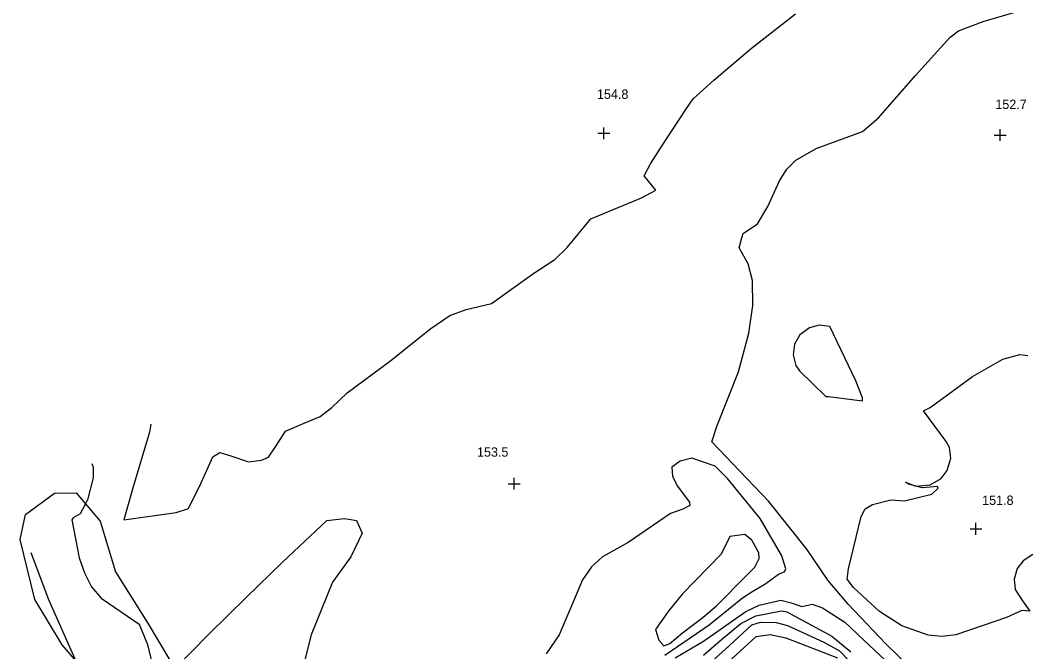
# Model space of a CAD drawing. Extents: x 1467615 to 2003689, y 770235 to 1108726.
# Drawn here: x 2002016.7 to 2002231.5, y 772441.5 to 772576.2 of the extents above; entities that cross this region are included whole.
import ezdxf

# ---------------------------------------------------------------- set-up
doc = ezdxf.new("R2010")
doc.units = 0
for name, color, linetype in [('RD_DTM_Major1', 7, 'Continuous'), ('RD_DTM_Minor1', 7, 'Continuous'), ('RD_DTM_Minor2', 7, 'Continuous'), ('RD_DTM_Obscure', 7, 'Continuous'), ('RD_DTM_Spot_Elev', 7, 'Continuous')]:
    doc.layers.add(name, color=color, linetype=linetype)

msp = doc.modelspace()

# ---------------------------------------------------------------- linework, layer by layer
at = {"layer": 'RD_DTM_Major1'}
for points in [[(2002166.11, 772462.36), (2002157.92, 772453.87), (2002154.87, 772450.14), (2002152.16, 772446.28), (2002152.83, 772444), (2002153.88, 772442.79), (2002155.19, 772443.3), (2002157.86, 772445.53), (2002162.27, 772448.91), (2002165.15, 772451.3), (2002171.7, 772457.89), (2002173.34, 772459.55), (2002174.25, 772461.39), (2002174.15, 772462.61), (2002172.67, 772465.31), (2002171.21, 772466.52), (2002167.98, 772466.13), (2002166.11, 772462.36)], [(2002165.01, 772436.89), (2002173.6, 772444.79), (2002176.56, 772445.18), (2002179.95, 772444.48), (2002190.92, 772440.2)]]:
    msp.add_lwpolyline(points, dxfattribs=at)
at = {"layer": 'RD_DTM_Minor1'}
for points in [[(2002044.54, 772490.04), (2002044.27, 772488.35), (2002040.75, 772476.72), (2002038.81, 772469.64), (2002049.96, 772471.18), (2002052.6, 772472.04), (2002055.31, 772477.54), (2002057.77, 772483.1), (2002059.24, 772483.98), (2002061.57, 772483.33), (2002065.36, 772482.02), (2002068.11, 772482.35), (2002069.61, 772483.02), (2002071.15, 772485.24), (2002073.27, 772488.57), (2002077.24, 772490.27), (2002080.62, 772491.65), (2002083.14, 772493.58), (2002086.43, 772496.71), (2002095.44, 772503.43), (2002104.25, 772510.44), (2002108.26, 772513.21), (2002111.77, 772514.5), (2002117.17, 772515.76), (2002126.21, 772522.26), (2002130.66, 772525.14), (2002133.31, 772527.73), (2002138.36, 772533.86), (2002149.14, 772538.32), (2002152.18, 772539.97), (2002149.75, 772543.03), (2002151.06, 772545.57), (2002153.86, 772549.92), (2002158.75, 772557.37), (2002160.19, 772559.45), (2002164.56, 772563.39), (2002172.59, 772570.25), (2002182.01, 772577.54)], [(2002209.1, 772435.53), (2002201.18, 772443.27), (2002193.23, 772451.64), (2002188.91, 772456.79), (2002184.37, 772463.39), (2002176.33, 772473.59), (2002168.52, 772481.69), (2002164.15, 772486.31), (2002165.27, 772489.78), (2002169.82, 772501.24), (2002172.04, 772509.44), (2002172.9, 772515.36), (2002172.85, 772520.68), (2002171.88, 772524.23), (2002169.99, 772527.67), (2002170.55, 772529.76), (2002170.81, 772530.7), (2002173.87, 772532.76), (2002176.05, 772536.49), (2002178.54, 772541.92), (2002180.14, 772544.41), (2002182.06, 772546.35), (2002186.37, 772548.79), (2002196.27, 772552.42), (2002199.65, 772555.38), (2002207.6, 772564.36), (2002214.96, 772572.57), (2002216.74, 772573.9), (2002221.97, 772575.87), (2002231.41, 772578.68)], [(2002188.46, 772495.97), (2002189.04, 772495.96), (2002196.25, 772495.02), (2002196.28, 772495.65), (2002194.87, 772499.26), (2002189.27, 772510.84), (2002187.06, 772511.13), (2002185, 772510.62), (2002182.92, 772509.09), (2002181.78, 772507.08), (2002181.46, 772504.85), (2002182.07, 772502.54), (2002182.87, 772501.45), (2002188.46, 772495.97)], [(2002232.57, 772462.24), (2002230.53, 772460.9), (2002229.27, 772459.25), (2002228.62, 772457), (2002228.84, 772454.81), (2002230.35, 772452.4), (2002231.93, 772450.17), (2002230.24, 772450.3), (2002226.97, 772448.85), (2002216.17, 772445.11), (2002213.21, 772444.78), (2002210.24, 772445.05), (2002204.62, 772447.03), (2002199.89, 772450.07), (2002194.38, 772455.21), (2002192.98, 772457.01), (2002193.27, 772459.22), (2002195.97, 772470.35), (2002196.82, 772472.02), (2002198.37, 772472.9), (2002202.32, 772473.94), (2002205.2, 772473.71), (2002211.07, 772475.11), (2002212.37, 772476.42), (2002212.23, 772476.79), (2002209.05, 772476.5), (2002206.09, 772477.22), (2002205.43, 772477.67), (2002207.65, 772476.86), (2002210.72, 772477.09), (2002213.01, 772478.47), (2002214.35, 772480.18), (2002215.08, 772482.81), (2002214.79, 772485.08), (2002214.07, 772486.32), (2002209.26, 772492.88), (2002210.66, 772493.63), (2002219.7, 772500.19), (2002226.16, 772503.94), (2002229.8, 772504.91), (2002231.53, 772504.66)], [(2002154.11, 772440.78), (2002163.58, 772447.26), (2002170.7, 772453.04), (2002172.86, 772454.46), (2002175.67, 772456.06), (2002178.36, 772458.07), (2002179.67, 772458.57), (2002179.9, 772459.21), (2002179.05, 772461.99), (2002174.46, 772469.95), (2002167.5, 772478.44), (2002164.84, 772481.11), (2002159.91, 772482.78), (2002157.43, 772482.17), (2002155.63, 772480.87), (2002155.77, 772478.99), (2002156.73, 772476.91), (2002159.39, 772473.39), (2002159.44, 772472.7), (2002157.94, 772471.94), (2002155.31, 772470.97), (2002146.34, 772464.79), (2002140.87, 772461.77), (2002138.47, 772459.62), (2002136.58, 772456.85), (2002133.9, 772450.49), (2002131.59, 772445.11), (2002128.82, 772441.07)], [(2002031.98, 772481.64), (2002032.24, 772480.86), (2002032.25, 772478.64), (2002031.06, 772473.93), (2002030.61, 772473.08)], [(2002049.21, 772437.44), (2002056.93, 772445.27), (2002064.89, 772453.08), (2002072.64, 772460.63), (2002082.1, 772469.53), (2002085.77, 772469.96), (2002086.76, 772469.81), (2002088.37, 772469.54), (2002089.57, 772466.84), (2002087.17, 772461.75), (2002083.28, 772456.35), (2002078.7, 772445.16), (2002077.07, 772438.66)], [(2002156.36, 772440.23), (2002162.35, 772443.76), (2002171.42, 772450.14), (2002174.24, 772451.43), (2002178.89, 772452.53), (2002181.07, 772451.93), (2002183.34, 772451.2), (2002185.55, 772451.66), (2002187.75, 772450.88), (2002192.47, 772447.86), (2002196.46, 772444.04), (2002204.64, 772436.37)], [(2002162.38, 772440.8), (2002166.23, 772444.11), (2002170.32, 772447.56), (2002173.55, 772449.21), (2002178.97, 772450.28), (2002180.16, 772450.03), (2002189.74, 772444.85), (2002193.77, 772441.47)], [(2002161.74, 772437.25), (2002167.9, 772442.84), (2002172.64, 772447.24), (2002174.51, 772447.81), (2002177.86, 772447.73), (2002180.31, 772447.11), (2002187.99, 772443.6), (2002191.35, 772441.74), (2002193.47, 772439.52)]]:
    msp.add_lwpolyline(points, dxfattribs=at)
at = {"layer": 'RD_DTM_Minor2'}
for points in [[(2002030.61, 772473.08), (2002029.48, 772470.91), (2002027.97, 772470.06), (2002027.72, 772469.67), (2002029.3, 772461.58), (2002030.38, 772458.32), (2002031.92, 772455.34), (2002033.96, 772452.98), (2002038.46, 772449.89), (2002042.05, 772447.39), (2002043.84, 772443.04), (2002044.96, 772438.32), (2002046.39, 772437.3), (2002048.93, 772437.16), (2002049.21, 772437.44)], [(2002018.98, 772462.66), (2002022.7, 772452.67), (2002028.31, 772440.02), (2002028.55, 772439.6)]]:
    msp.add_lwpolyline(points, dxfattribs=at)
at = {"layer": 'RD_DTM_Obscure'}
msp.add_lwpolyline([(2002037.57, 772429.15), (2002033.12, 772434.3), (2002025.65, 772442.97), (2002019.8, 772452.67), (2002016.69, 772465.45), (2002017.85, 772470.77), (2002023.98, 772475.34), (2002028.62, 772475.38), (2002033.78, 772469.4), (2002037.03, 772458.54), (2002043.77, 772447.8), (2002048.59, 772439.72), (2002050.26, 772433.61), (2002047.39, 772426.1), (2002037.57, 772429.15)], dxfattribs=at)
at = {"layer": 'RD_DTM_Spot_Elev'}
for p, q in [((2002139.87, 772552.06), (2002142.37, 772552.06)), ((2002141.12, 772550.81), (2002141.12, 772553.31)), ((2002224.36, 772551.69), (2002226.86, 772551.69)), ((2002225.61, 772550.44), (2002225.61, 772552.94)), ((2002122, 772476.11), (2002122, 772478.61)), ((2002120.75, 772477.36), (2002123.25, 772477.36)), ((2002219.2, 772467.73), (2002221.7, 772467.73)), ((2002220.45, 772466.48), (2002220.45, 772468.98))]:
    msp.add_line(p, q, dxfattribs=at)

# ---------------------------------------------------------------- texts
for s, p in [('154.8', (2002139.66, 772559.41)), ('152.7', (2002224.59, 772557.25)), ('153.5', (2002114.08, 772483.11)), ('151.8', (2002221.78, 772472.83))]:
    msp.add_text(s, height=2, dxfattribs=at).set_placement(p)

doc.saveas('drawing.dxf')
